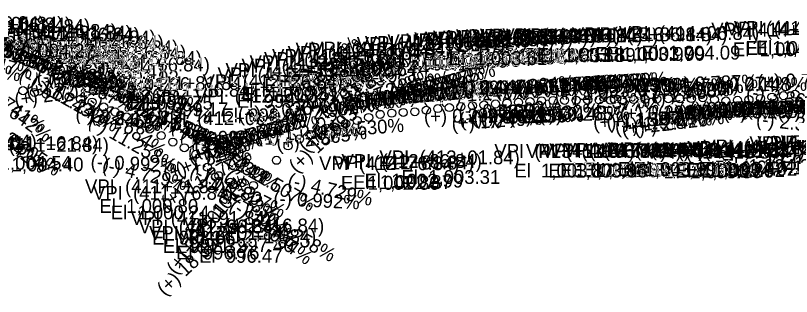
# Model space of a CAD drawing. Extents: x 16972137 to 16976737, y 12558490 to 12559551.
# Drawn here: x 16975501.5 to 16975838.2, y 12558873.6 to 12558995.3 of the extents above; entities that cross this region are included whole.
import ezdxf

# ---------------------------------------------------------------- set-up
doc = ezdxf.new("R2010")
doc.units = 0
doc.layers.add('RD_DDB_GradeTX', color=7, linetype='Continuous')
doc.layers.add('RD_DDB_PI', color=7, linetype='Continuous')

msp = doc.modelspace()

# ---------------------------------------------------------------- linework, layer by layer
at = {"layer": 'RD_DDB_PI'}
for centre in [(16975504.74, 12558962.77), (16975509.74, 12558962.01), (16975514.74, 12558961.3), (16975519.74, 12558960.64), (16975524.74, 12558959.95), (16975779.74, 12558959.18), (16975784.74, 12558959.25), (16975789.74, 12558959.29), (16975794.74, 12558959.35), (16975799.74, 12558959.75), (16975824.74, 12558959.4), (16975829.74, 12558959.99), (16975834.74, 12558960.6), (16975839.74, 12558961.22), (16975529.74, 12558959.09), (16975534.74, 12558957.83), (16975694.74, 12558955.86), (16975699.74, 12558956.24), (16975704.74, 12558956.62), (16975709.74, 12558957), (16975714.74, 12558957.37), (16975719.74, 12558957.71), (16975724.74, 12558958.05), (16975729.74, 12558958.39), (16975734.74, 12558958.51), (16975739.74, 12558958.58), (16975744.74, 12558958.65), (16975749.74, 12558958.73), (16975754.74, 12558958.76), (16975759.74, 12558958.64), (16975764.74, 12558958.76), (16975769.74, 12558958.9), (16975774.74, 12558959.04), (16975804.74, 12558958.91), (16975809.74, 12558958.32), (16975814.74, 12558958.6), (16975819.74, 12558958.9), (16975539.74, 12558955.69), (16975544.74, 12558953.52), (16975659.74, 12558952.51), (16975664.74, 12558953.02), (16975669.74, 12558953.33), (16975674.74, 12558953.64), (16975679.74, 12558954.28), (16975684.74, 12558955.01), (16975689.74, 12558955.47), (16975549.74, 12558951.35), (16975649.74, 12558949.82), (16975654.74, 12558951.16), (16975554.74, 12558948.93), (16975559.74, 12558946.12), (16975639.74, 12558947.13), (16975644.74, 12558948.48), (16975564.74, 12558943.31), (16975629.74, 12558943.72), (16975634.74, 12558945.59), (16975569.74, 12558940.5), (16975624.74, 12558941.84), (16975574.74, 12558938.04), (16975619.74, 12558938.87), (16975579.74, 12558935.17), (16975614.74, 12558932.6), (16975584.74, 12558929.59), (16975589.74, 12558925.92), (16975609.74, 12558926.32), (16975594.74, 12558923.11), (16975599.74, 12558922.86), (16975604.74, 12558921.68)]:
    msp.add_circle(centre, 1.75, dxfattribs=at)

# ---------------------------------------------------------------- texts
at = {"layer": 'RD_DDB_GradeTX'}
for s, rotation, p in [('(-) 8.555%', 336.8409, (16975479.91, 12558984.55)), ('(-) 8.686%', 336.5257, (16975485.61, 12558982.47)), ('(-) 8.686%', 336.5257, (16975490.61, 12558980.3)), ('(-) 9.687%', 334.1562, (16975497.12, 12558980.17)), ('(-) 11.243%', 330.6567, (16975503.47, 12558981.19)), ('(+) 25.101%', 51.4525, (16975624.12, 12558949.19)), ('(-) 5.047%', 345.8371, (16975471.76, 12558976.82)), ('(-) 3.431%', 350.2663, (16975466.36, 12558973.01)), ('(-) 22.304%', 311.8832, (16975531.45, 12558975.54)), ('(+) 11.870%', 30.6881, (16975634.95, 12558951.39)), ('(-) 9.807%', 333.8798, (16975517.17, 12558969.61)), ('(-) 11.507%', 330.0851, (16975524.33, 12558970.51)), ('(+) 5.375%', 15.0437, (16975672.08, 12558958.93)), ('(-) 13.741%', 325.5091, (16975477.34, 12558967.72)), ('(-) 11.243%', 330.6567, (16975502.59, 12558967.92)), ('(+) 5.018%', 14.0851, (16975506.85, 12558959.03)), ('(-) 0.891%', 357.4484, (16975510.62, 12558966.09)), ('(-) 1.299%', 356.2842, (16975515.54, 12558965.45)), ('(+) 25.101%', 51.4525, (16975628.51, 12558935.43)), ('(+) 7.488%', 20.5259, (16975646.87, 12558953.34)), ('(+) 6.150%', 17.092, (16975653.6, 12558954.53)), ('(+) 5.375%', 15.0437, (16975662.08, 12558956.24)), ('(+) 5.375%', 15.0437, (16975667.08, 12558957.59)), ('(+) 1.370%', 3.9181, (16975745.14, 12558962.45)), ('(+) 0.722%', 2.0675, (16975823.5, 12558963.65)), ('(-) 14.642%', 323.7924, (16975480.75, 12558964.74)), ('(-) 11.243%', 330.6567, (16975507.59, 12558965.11)), ('(-) 2.789%', 352.0614, (16975519.15, 12558963.79)), ('(-) 3.065%', 351.2879, (16975523.68, 12558962.91)), ('(+) 7.524%', 20.6166, (16975641.52, 12558951.36)), ('(+) 5.375%', 15.0437, (16975657.08, 12558954.9)), ('(+) 0.147%', 0.4204, (16975690.78, 12558961.29)), ('(+) 1.864%', 5.3242, (16975705.26, 12558959.93)), ('(+) 1.530%', 4.3757, (16975709.69, 12558960.01)), ('(+) 0.274%', 0.7847, (16975718.88, 12558961.35)), ('(+) 1.530%', 4.3757, (16975719.69, 12558960.77)), ('(+) 1.530%', 4.3757, (16975724.69, 12558961.16)), ('(+) 1.450%', 4.1457, (16975730.12, 12558961.49)), ('(+) 1.370%', 3.9181, (16975735.14, 12558961.77)), ('(+) 1.370%', 3.9181, (16975740.14, 12558962.11)), ('(+) 0.463%', 1.3272, (16975748.6, 12558961.83)), ('(+) 0.290%', 0.8315, (16975753.57, 12558961.78)), ('(+) 0.290%', 0.8315, (16975758.57, 12558961.86)), ('(+) 0.147%', 0.4204, (16975770.78, 12558961.88)), ('(+) 2.093%', 5.9736, (16975778.37, 12558957.81)), ('(+) 0.787%', 2.2534, (16975784.26, 12558962.36)), ('(+) 0.274%', 0.7847, (16975798.87, 12558962.44)), ('(+) 0.148%', 0.4231, (16975805.49, 12558962.4)), ('(+) 2.701%', 7.6924, (16975501.47, 12558955.94)), ('(-) 2.765%', 352.1274, (16975539.03, 12558961)), ('(-) 3.431%', 350.2663, (16975545.14, 12558959.5)), ('(+) 1.450%', 4.1457, (16975650.34, 12558955.71)), ('(+) 1.370%', 3.9181, (16975655.34, 12558956.3)), ('(+) 1.370%', 3.9181, (16975660.34, 12558956.65)), ('(+) 1.370%', 3.9181, (16975665.34, 12558956.99)), ('(+) 0.463%', 1.3272, (16975668.63, 12558959.98)), ('(+) 0.290%', 0.8315, (16975673.58, 12558960.62)), ('(+) 2.036%', 5.813, (16975677.92, 12558957.37)), ('(+) 0.290%', 0.8317, (16975683.58, 12558960.77)), ('(+) 1.249%', 3.5746, (16975685.16, 12558957.3)), ('(+) 0.577%', 1.6513, (16975714.15, 12558960.29)), ('(+) 1.597%', 4.5659, (16975735.65, 12558957.64)), ('(-) 3.363%', 350.4538, (16975737.4, 12558961.11)), ('(+) 2.468%', 7.0355, (16975773.87, 12558956.11)), ('(-) 0.507%', 358.5486, (16975773.98, 12558961.28)), ('(-) 3.363%', 350.4538, (16975818.21, 12558959.69)), ('(-) 14.684%', 323.7142, (16975530.31, 12558958.39)), ('(-) 5.047%', 345.8371, (16975549.18, 12558957.28)), ('(+) 1.864%', 5.3242, (16975625.63, 12558952.51)), ('(+) 1.530%', 4.3757, (16975634.94, 12558954.29)), ('(+) 1.530%', 4.3757, (16975639.94, 12558954.67)), ('(+) 1.530%', 4.3757, (16975644.94, 12558955.05)), ('(-) 2.377%', 353.2234, (16975743.2, 12558957.16)), ('(+) 1.597%', 4.5659, (16975816.34, 12558952.05)), ('(-) 8.555%', 336.8409, (16975553.06, 12558953.26)), ('(+) 2.036%', 5.813, (16975598.36, 12558949.27)), ('(+) 2.902%', 8.255, (16975618.64, 12558948.45)), ('(+) 18.593%', 42.912, (16975623.48, 12558926.81)), ('(-) 0.507%', 358.5486, (16975693.71, 12558951.31)), ('(+) 2.565%', 7.3071, (16975694.38, 12558947.08)), ('(+) 2.902%', 8.255, (16975699.48, 12558948.05)), ('(+) 0.460%', 1.317, (16975789.2, 12558951.54)), ('(+) 0.482%', 1.3806, (16975793.86, 12558951.58)), ('(+) 0.577%', 1.6513, (16975794.46, 12558950.6)), ('(+) 0.504%', 1.4441, (16975798.99, 12558951.64)), ('(+) 0.526%', 1.5076, (16975803.76, 12558951.69)), ('(+) 0.549%', 1.5711, (16975809.13, 12558951.76)), ('(+) 0.571%', 1.6344, (16975815.85, 12558951.88)), ('(+) 0.593%', 1.6977, (16975818.74, 12558951.9)), ('(+) 0.668%', 1.9138, (16975829.31, 12558952.01)), ('(+) 1.152%', 3.2961, (16975832.17, 12558950.59)), ('(+) 0.697%', 1.9946, (16975834.62, 12558952.11)), ('(-) 14.642%', 323.7924, (16975478.66, 12558951.39)), ('(-) 2.846%', 351.9003, (16975527.28, 12558950.42)), ('(-) 2.614%', 352.5549, (16975534.05, 12558949.7)), ('(-) 8.686%', 336.5257, (16975558.58, 12558950.78)), ('(+) 0.290%', 0.8315, (16975678.76, 12558948.7)), ('(+) 0.512%', 1.4662, (16975700.29, 12558948.11)), ('(+) 0.533%', 1.5279, (16975703.29, 12558948.12)), ('(+) 0.555%', 1.5897, (16975708.66, 12558948.2)), ('(+) 1.530%', 4.3757, (16975715.61, 12558948.43)), ('(+) 0.148%', 0.4231, (16975725.58, 12558949.81)), ('(+) 0.265%', 0.7579, (16975728.63, 12558949.48)), ('(+) 1.152%', 3.2961, (16975752.31, 12558945.99)), ('(+) 1.197%', 3.424, (16975758.11, 12558946.2)), ('(+) 0.290%', 0.8317, (16975763.75, 12558949.93)), ('(+) 2.426%', 6.9169, (16975770.07, 12558943.69)), ('(+) 0.512%', 1.4662, (16975780.26, 12558950.16)), ('(+) 0.533%', 1.5279, (16975783.26, 12558950.26)), ('(+) 0.555%', 1.5897, (16975788.63, 12558950.42)), ('(+) 0.265%', 0.7579, (16975808.62, 12558950.54)), ('(-) 13.305%', 326.3658, (16975483.75, 12558948.61)), ('(-) 11.258%', 330.6258, (16975532.65, 12558947.73)), ('(-) 8.686%', 336.5257, (16975563.58, 12558948.61)), ('(+) 5.375%', 15.0437, (16975584.99, 12558935.52)), ('(+) 5.375%', 15.0437, (16975589.99, 12558936.87)), ('(+) 5.375%', 15.0437, (16975594.99, 12558938.21)), ('(+) 1.530%', 4.3757, (16975630.85, 12558941.94)), ('(+) 1.249%', 3.5746, (16975690.91, 12558945.63)), ('(+) 1.975%', 5.6385, (16975761.88, 12558944.15)), ('(+) 2.384%', 6.7979, (16975764.86, 12558943.2)), ('(-) 2.377%', 353.2234, (16975822.6, 12558947.73)), ('(-) 9.687%', 334.1562, (16975568.62, 12558945.54)), ('(+) 6.150%', 17.092, (16975577.35, 12558931.09)), ('(+) 5.375%', 15.0437, (16975579.99, 12558934.18)), ('(+) 1.249%', 3.5746, (16975606.08, 12558940.33)), ('(+) 1.249%', 3.5746, (16975611.08, 12558940.65)), ('(+) 2.565%', 7.3071, (16975615.07, 12558936.91)), ('(+) 7.488%', 20.5259, (16975572.26, 12558925.41)), ('(-) 11.243%', 330.6567, (16975572.56, 12558942.35)), ('(-) 11.243%', 330.6567, (16975577.56, 12558939.54)), ('(+) 7.524%', 20.6166, (16975566.96, 12558923.31)), ('(+) 11.870%', 30.6881, (16975566.86, 12558910.98)), ('(-) 0.992%', 357.1603, (16975533.97, 12558929.12)), ('(-) 11.507%', 330.0851, (16975593.01, 12558930.99)), ('(-) 4.729%', 346.6963, (16975538.72, 12558928.04)), ('(-) 11.243%', 330.6567, (16975576.68, 12558926.27)), ('(-) 9.807%', 333.8798, (16975583.21, 12558923.87)), ('(-) 22.304%', 311.8832, (16975592.13, 12558925.84)), ('(+) 25.101%', 51.4525, (16975576.15, 12558888.98)), ('(-) 4.729%', 346.6963, (16975619.21, 12558921.34)), ('(+) 25.101%', 51.4525, (16975571.15, 12558882.71)), ('(-) 0.992%', 357.1603, (16975613.27, 12558913.18)), ('(-) 14.684%', 323.7142, (16975593.82, 12558911.76)), ('(-) 11.258%', 330.6258, (16975601.73, 12558908.85)), ('(+) 18.593%', 42.912, (16975566.23, 12558873.58))]:
    msp.add_text(s, height=6, rotation=rotation, dxfattribs=at).set_placement(p)
at = {"layer": 'RD_DDB_PI'}
for s, p in [('VPI  (410+96.84)', (16975453.27, 12558989.02)), ('VPI  (411+01.84)', (16975461.35, 12558988.79)), ('VPI  (411+06.84)', (16975464.81, 12558988.47)), ('VPI  (411+11.84)', (16975473, 12558987.77)), ('VPI  (411+26.84)', (16975484.57, 12558985.64)), ('VPI  (411+31.84)', (16975491.05, 12558984.95)), ('VPI  (414+46.84)', (16975803.39, 12558986.22)), ('VPI  (414+51.84)', (16975809.69, 12558986.74)), ('VPI  (414+56.84)', (16975813.16, 12558986.94)), ('VPI  (411+36.84)', (16975494.51, 12558984.09)), ('VPI  (411+41.84)', (16975501.46, 12558982.83)), ('VPI  (413+11.84)', (16975671.05, 12558981.62)), ('VPI  (413+16.84)', (16975674.51, 12558982)), ('VPI  (413+21.84)', (16975679.16, 12558982.37)), ('VPI  (413+26.84)', (16975682.63, 12558982.71)), ('VPI  (413+31.84)', (16975689.1, 12558983.05)), ('VPI  (413+36.84)', (16975692.57, 12558983.39)), ('VPI  (413+41.84)', (16975699.51, 12558983.51)), ('VPI  (413+46.84)', (16975702.98, 12558983.58)), ('VPI  (413+56.84)', (16975712.74, 12558983.73)), ('VPI  (413+61.84)', (16975719.51, 12558983.76)), ('VPI  (413+86.84)', (16975742.86, 12558984.18)), ('VPI  (413+91.84)', (16975749.51, 12558984.25)), ('VPI  (414+06.84)', (16975763.27, 12558984.75)), ('El  1,004.94', (16975463.28, 12558980.52)), ('El  1,004.90', (16975468.17, 12558980.29)), ('El  1,004.83', (16975472.78, 12558979.97)), ('El  1,004.69', (16975478.28, 12558979.27)), ('VPI  (411+46.84)', (16975504.93, 12558980.69)), ('VPI  (411+51.84)', (16975511.23, 12558978.52)), ('VPI  (412+91.84)', (16975649.57, 12558980.01)), ('VPI  (412+96.84)', (16975653.04, 12558980.47)), ('VPI  (413+06.84)', (16975662.86, 12558981.24)), ('El  1,004.49', (16975818.28, 12558978.24)), ('El  1,004.53', (16975822.66, 12558978.44)), ('El  1,004.27', (16975493.11, 12558977.14)), ('El  1,004.13', (16975499.44, 12558976.45)), ('El  1,003.96', (16975502.87, 12558975.59)), ('VPI  (411+56.84)', (16975514.69, 12558976.35)), ('VPI  (412+56.84)', (16975612.8, 12558974.82)), ('VPI  (412+61.84)', (16975619.57, 12558976.16)), ('VPI  (412+66.84)', (16975623.04, 12558977.51)), ('VPI  (412+71.84)', (16975629.75, 12558978.02)), ('El  1,003.82', (16975702.43, 12558974.89)), ('El  1,003.84', (16975707.75, 12558975.01)), ('El  1,003.85', (16975712.55, 12558975.08)), ('El  1,003.88', (16975722.66, 12558975.23)), ('El  1,003.89', (16975727.75, 12558975.26)), ('El  1,003.97', (16975753.05, 12558975.68)), ('El  1,003.99', (16975757.87, 12558975.75)), ('El  1,004.09', (16975773.17, 12558976.25)), ('El  1,004.38', (16975812.78, 12558977.72)), ('El  1,003.70', (16975507.93, 12558974.33)), ('El  1,003.28', (16975512.43, 12558972.19)), ('VPI  (411+61.84)', (16975521.46, 12558973.93)), ('VPI  (412+46.84)', (16975603.04, 12558972.13)), ('VPI  (412+51.84)', (16975609.34, 12558973.48)), ('El  1,003.14', (16975659.41, 12558971.51)), ('El  1,003.23', (16975662.13, 12558971.97)), ('El  1,003.39', (16975672.46, 12558972.74)), ('El  1,003.46', (16975677.87, 12558973.12)), ('El  1,003.54', (16975682.64, 12558973.5)), ('El  1,003.61', (16975689.41, 12558973.87)), ('El  1,003.68', (16975692.78, 12558974.21)), ('El  1,003.75', (16975697.84, 12558974.55)), ('El  1,002.84', (16975517.81, 12558970.02)), ('VPI  (411+66.84)', (16975524.93, 12558971.12)), ('VPI  (412+36.84)', (16975592.63, 12558968.72)), ('VPI  (412+41.84)', (16975599.57, 12558970.59)), ('El  1,002.64', (16975632.93, 12558969.01)), ('El  1,002.74', (16975638.11, 12558969.52)), ('El  1,002.41', (16975524.47, 12558967.85)), ('El  1,001.92', (16975529.5, 12558965.43)), ('VPI  (412+31.84)', (16975589.16, 12558966.84)), ('El  1,001.83', (16975619.32, 12558964.98)), ('El  1,002.10', (16975624.35, 12558966.32)), ('El  1,002.37', (16975627.69, 12558967.66)), ('El  1,001.36', (16975534.41, 12558962.62)), ('VPI  (411+81.84)', (16975541.35, 12558963.04)), ('VPI  (412+26.84)', (16975582.68, 12558963.87)), ('El  1,001.26', (16975609.47, 12558962.09)), ('El  1,001.56', (16975614.58, 12558963.63)), ('VPI  (411+86.84)', (16975544.81, 12558960.17)), ('El  1,000.51', (16975599.47, 12558958.34)), ('El  1,000.88', (16975602.96, 12558960.22)), ('VPI  (412+21.84)', (16975579.22, 12558957.6)), ('El  999.91', (16975597.54, 12558955.37)), ('El  999.75', (16975550.97, 12558954.54)), ('El  999.17', (16975557.71, 12558951.67)), ('VPI  (412+06.84)', (16975562.92, 12558947.86)), ('El  998.66', (16975590.88, 12558949.1)), ('VPI  (410+91.84)', (16975449.81, 12558937.76)), ('El  996.71', (16975577.71, 12558939.36)), ('VPI  (410+86.84)', (16975443.16, 12558937.09)), ('VPI  (411+16.84)', (16975476.46, 12558937.01)), ('VPI  (411+21.84)', (16975481.11, 12558936.3)), ('VPI  (414+31.84)', (16975789.51, 12558934.4)), ('VPI  (414+36.84)', (16975792.98, 12558934.99)), ('VPI  (414+41.84)', (16975799.93, 12558935.6)), ('VPI  (414+61.84)', (16975819.93, 12558937.05)), ('VPI  (414+66.84)', (16975823.39, 12558937.17)), ('VPI  (414+71.84)', (16975830.11, 12558937.3)), ('VPI  (414+76.84)', (16975833.57, 12558937.43)), ('VPI  (413+51.84)', (16975709.28, 12558933.65)), ('VPI  (413+66.84)', (16975722.98, 12558933.64)), ('VPI  (413+71.84)', (16975729.69, 12558933.76)), ('VPI  (413+76.84)', (16975733.16, 12558933.9)), ('VPI  (413+81.84)', (16975739.4, 12558934.04)), ('VPI  (413+96.84)', (16975752.98, 12558934.29)), ('VPI  (414+01.84)', (16975759.81, 12558934.35)), ('VPI  (414+11.84)', (16975771.46, 12558933.91)), ('VPI  (414+16.84)', (16975774.93, 12558933.32)), ('VPI  (414+21.84)', (16975779.57, 12558933.6)), ('VPI  (414+26.84)', (16975783.04, 12558933.9)), ('El  1,004.54', (16975483.05, 12558928.51)), ('El  1,004.40', (16975488.17, 12558927.8)), ('VPI  (412+76.84)', (16975633.22, 12558928.33)), ('VPI  (412+81.84)', (16975639.46, 12558928.64)), ('VPI  (412+86.84)', (16975642.92, 12558929.28)), ('VPI  (413+01.84)', (16975659.4, 12558930.86)), ('El  1,004.55', (16975827.84, 12558928.55)), ('El  1,004.57', (16975833.23, 12558928.67)), ('El  1,003.87', (16975717.93, 12558925.15)), ('El  1,003.86', (16975732.75, 12558925.14)), ('El  1,003.89', (16975737.75, 12558925.26)), ('El  1,003.92', (16975742.55, 12558925.4)), ('El  1,003.94', (16975747.87, 12558925.54)), ('El  1,003.99', (16975762.87, 12558925.79)), ('El  1,004.01', (16975769.7, 12558925.85)), ('El  1,003.92', (16975777.55, 12558925.41)), ('El  1,003.80', (16975782.64, 12558924.82)), ('El  1,003.86', (16975787.75, 12558925.1)), ('El  1,003.92', (16975792.55, 12558925.4)), ('El  1,004.02', (16975797.84, 12558925.9)), ('El  1,004.14', (16975804.82, 12558926.49)), ('El  1,004.26', (16975807.93, 12558927.1)), ('El  1,003.31', (16975668.99, 12558922.36)), ('VPI  (411+71.84)', (16975531.64, 12558918.31)), ('El  1,002.80', (16975642.69, 12558919.83)), ('El  1,002.87', (16975647.99, 12558920.14)), ('El  1,002.99', (16975652.93, 12558920.78)), ('VPI  (411+76.84)', (16975535.11, 12558915.5)), ('El  1,000.80', (16975537.93, 12558909.81)), ('El  1,000.24', (16975542.81, 12558907)), ('VPI  (411+91.84)', (16975551.46, 12558904.59)), ('VPI  (411+96.84)', (16975554.93, 12558900.92)), ('VPI  (412+16.84)', (16975574.57, 12558901.32)), ('VPI  (412+01.84)', (16975559.46, 12558898.11)), ('El  998.06', (16975560.76, 12558896.09)), ('VPI  (412+11.84)', (16975571.11, 12558896.68)), ('El  997.32', (16975565.44, 12558892.42)), ('El  997.40', (16975586.06, 12558892.82)), ('El  996.76', (16975571.18, 12558889.61)), ('El  996.47', (16975581.18, 12558888.18))]:
    msp.add_text(s, height=6, dxfattribs=at).set_placement(p)

doc.saveas('drawing.dxf')
